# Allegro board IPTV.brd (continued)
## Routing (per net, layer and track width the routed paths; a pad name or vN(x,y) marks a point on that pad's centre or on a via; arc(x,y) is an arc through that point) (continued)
VCC_3.3V: length 38.9
  TOP w0.203: C333.1 129.39,49.72 129.39,49.31 128.08,48.01 U18.49 ; 119.8,50.1 120.24,50.1 120.44,49.9 U18.68 ; U18.20 121.24,40.89 v1(121.1,40.75) 120.84,41.01 U18.19 ; 117.32,46.52 118.72,46.52 119.01,46.81 U18.6 ; U18.30 125.24,41.15 125.45,40.93 125.48,40.93 v1(125.53,40.88) 125.54,40.89 125.54,40.93 125.64,41.02 U18.31 ; v1(125.67,50.63) 125.63,50.58 125.58,50.58 125.24,50.24 U18.56
  TOP w0.406: v1(131.36,36.99) C211.1 v1(130.28,35.85) ; v1(116.56,50.08) C245.1 116.59,50.86 C330.1 118.7,50.86 119.46,50.1 119.8,50.1 ; C333.1 v1(130.2,49.85) 131.11,49.85 C364.1 ; 117.32,46.52 C342.1 116.03,47.2 v1(116.03,47.21) ; R344.1 v1(116.69,47.15) ; C339.2 135.36,56.68 ; R320.1 v1(134.47,47.79) ; v1(115.8,52.08) R29.2 ; R338.2 v1(133.68,51.98) ; v1(117.35,50.18) R335.1 ; R321.1 v1(130.79,37.63) ; C371.2 v1(132.18,36.99)
  BOTTOM w0.406: v1(121.1,40.75) 121.04,40.7 121.01,40.7 120.73,40.42 C362.1 ; R321.1 v1(130.79,37.63) ; v1(119.79,39.66) 119.84,39.71 C362.1 ; C246.1 125.43,51.05 125.67,50.81 v1(125.67,50.63) ; C369.1 v1(134.47,47.79) ; C244.1 C362.1 ; C368.1 111.23,40.68 ; C218.1 133.68,51.98 v1(133.68,51.98) ; v1(125.53,40.88) 125.73,40.88 C370.1 C316.1 ; R335.1 v1(117.35,50.18)
  vias: v1(111.4,39.66) v1(111.4,38.9) v1(111.4,38.14) v1(111.4,37.38) v1(134.6,57.31) v1(134.6,56.55)
VCC_SCI\G: length 14.7
  TOP w0.406: U12.4 v1(25.46,43.62)
  BOTTOM w0.406: R8.1 18.71,37.57 Q9.3 v1(21.31,37.5) ; v1(22.99,36.07) R148.2 ; C146.1 v1(21.97,43.05) ; v1(22.99,38.61) R149.2 ; R152.2 v1(23.6,55.12) ; v1(22.99,33.66) R147.2 ; v1(22.73,52.7) R151.2 ; v1(22.73,51.05) R150.2 ; R290.2 v1(21.84,43.69) ; C148.1 v1(23.75,43.05)
VDD1_2_RF_LDO: length 32.9
  TOP w0.406: R353.1 135.23,48.93 C248.1 v1(135.36,49.99) 135.36,51.03 R346.1 ; v1(133.58,40.8) FB3.1 FB2.1
  BOTTOM w0.508: v1(128.75,40.55) 129.01,40.8 v1(133.58,40.8) 134.85,40.8 135.36,41.31 v1(135.36,49.99) ; v1(128.75,40.55) R326.1 ; v1(128.75,40.55) 128.75,38.53 128.11,37.88 123.93,37.88 123.42,38.39 R333.2
VDD25OUT: length 36.7
  TOP w0.254: U1.12 v1(95.47,75.16) ; U1.1 v1(93.02,80.66) ; U1.24 v1(101.31,75.09) ; U1.33 v1(101.63,79.16)
  TOP w0.508: L48.1 v1(103.48,68.77) L50.2 ; v1(95.47,75.16) 96.32,76.01 100.4,76.01 v1(101.31,75.09)
  BOTTOM w0.406: v1(93.02,80.66) 93.26,80.43 C419.1 ; C421.1 101.68,79.21 v1(101.63,79.16)
  BOTTOM w0.508: v1(93.02,80.66) 93.02,75.33 93.21,75.14 C420.1 95.45,75.14 v1(95.47,75.16) ; v1(101.63,79.16) 101.63,78.45 100.85,77.67 C415.1 100.83,77.38 C412.2 100.83,75.58 v1(101.31,75.09) 104.12,72.29 104.12,69.4 v1(103.48,68.77)
VDD_AUDIO: length 12.4
  TOP w0.254: U22.9 66.29,104.97 65.56,105.7 C75.1 R247.2 v1(65.76,106.84)
  BOTTOM w0.381: R174.2 61.68,104.71 C203.1 65.38,107.23 v1(65.76,106.84)
VDDPLL: length 3.6
  TOP w0.203: C340.1 129.31,45.88 129.18,45.75 v1(128.75,45.75) 128.61,45.61 U18.43
  BOTTOM w0.406: R326.2 128.73,44.61 128.73,45.72 v1(128.75,45.75)
2G_0_SW_OUT: length 7.8
  TOP w0.254: R336.1 131.34,30.39 U21.5 C377.1 137.79,29.25 C324.2
2G_1_SW_OUT: length 8.5
  TOP w0.254: C372.2 120.12,22.49 C375.1 121.28,22.52 121.28,29.15 U19.5 121.26,29.71 R345.1
43227_VDDIN_RFL: length 8.9
  TOP w0.152: C336.1 134.77,48.37 133.3,48.37 R320.2 132.69,47.76 129.6,47.76 128.24,46.41 U18.45
/WDG_RSTN\G: length 27.2
  TOP w0.127: 84.35,26.92 84.35,27.97 IC13.D6
  TOP w0.152: R356.1 77.7,8.67 78.46,9.44 78.46,16.17 80.87,18.58 83.92,18.58 84.56,19.21 84.56,25.44 84.35,25.65 84.35,26.92
AFE_INPUT_VDD1P2: length 4.1
  TOP w0.203: U18.42 129.26,45.21 v1(129.31,45.25)
  BOTTOM w0.152: C326.1 129.39,46.42 R352.2 129.39,45.33 v1(129.31,45.25)
AUDIO_L\G: length 8.4
  TOP w0.254: XS9.B2 71.26,111.2 70.87,110.81 C392.2 70.84,110.12 R257.1
AUDIO_OUTL\G: length 43.5
  TOP w0.254: IC13.AV7 83.03,55.69 83.03,77.51 70.64,89.9 70.64,90.61 R175.1 70.64,91.32 70.64,92.54 70.9,92.81 C268.1
AUDIO_OUTR\G: length 43.5
  TOP w0.254: IC13.AV8 82.52,55.74 82.52,77.3 70.13,89.69 70.13,90.64 R362.1 70.13,91.3 70.13,92.57 69.89,92.81 C393.2
AUDIO_R\G: length 8.4
  TOP w0.254: R361.2 69.7,110.12 C394.2 69.67,110.81 69.28,111.2 XS9.C2
AVS_VREF_IO\G: length 4.2
  TOP w0.508: C90.1 R15.1 49.89,89.57 49.44,89.13 C87.2
BOOT_SEL0\G: length 10.8
  TOP w0.127: 89.13,42.33 88.95,42.33 88.75,42.12 87.25,42.12 87.01,42.36 85.96,42.36 IC13.AB4
  TOP w0.152: R39.1 93.41,42.33 93.09,42.65 R58.2 90.72,42.9 90.42,42.61 R40.1 89.13,42.33
BOOT_SEL1\G: length 9.6
  TOP w0.127: 89.28,41.41 88.76,41.41 88.62,41.56 85.96,41.56 IC13.AA4
  TOP w0.152: 89.28,41.41 90.19,41.41 R57.2 90.42,40.9 90.65,40.67 92.13,40.67 v1(92.3,40.84)
  BOTTOM w0.152: R83.1 R155.1 92.28,40.82 v1(92.3,40.84)
BSC_M0_SCL\G: length 79.3
  TOP w0.152: R140.1 v1(46.48,115.95) 47,116.47 XP1.15 ; v1(46.84,111.69) 46.84,111.52 47.19,111.16 48.13,111.16 48.31,110.98 48.31,110.65 48.16,110.5 47.83,110.5 47.68,110.35 47.68,110.02 47.85,109.84 48.18,109.84 48.44,109.59 48.44,109.16 65.71,91.88 65.71,88.54 74.16,80.1 74.16,56.5 73.55,55.9 IC13.AV19
  BOTTOM w0.152: v1(46.48,115.95) D10.2 47.03,114.62 47.03,111.89 v1(46.84,111.69) U14.3
BSC_M0_SDA\G: length 80.5
  TOP w0.152: v1(47.53,111.69) 47.53,111.8 47.75,112.03 48.67,112.03 48.95,111.75 48.95,110.07 66.65,92.37 66.65,88.92 75.11,80.46 75.11,56.86 73.96,55.7 73.96,55.17 IC13.AU19 ; R141.1 v1(47.88,115.95) 47.5,116.33 XP1.16
  BOTTOM w0.152: U14.4 v1(47.53,111.69) 47.33,111.89 47.33,114.62 D11.2 v1(47.88,115.95)
CLK_50M_PHY0\G: length 2.3
  TOP w0.152: IC8.9 20.42,84.55 19.88,85.09 R240.2
CORE0_RX: length 33.3
  TOP w0.152: v1(115.89,33.92) 115.89,42.8 117.06,43.97 119.1,43.97 119.13,44.01 U18.13 ; U21.6 C361.2 v1(130.81,32.45)
  BOTTOM w0.152: v1(115.89,33.92) 115.89,32.78 117.9,30.77 128.75,30.77 130.43,32.45 v1(130.81,32.45)
CORE0_TX: length 33.3
  TOP w0.152: v1(131.11,28.33) C366.2 U21.4 ; v1(116.4,31.25) 116.4,42.67 117.33,43.61 U18.14
  BOTTOM w0.152: v1(131.11,28.33) 124.71,28.33 124.21,28.84 118.81,28.84 v1(116.4,31.25)
CORE1_RX: length 18.1
  TOP w0.152: U18.16 118.59,42.81 118.53,42.86 117.89,42.86 117.54,42.51 117.54,30.43 118.75,29.22 C337.2 119.28,29.17 U19.4
CORE1_TX: length 23.2
  TOP w0.152: v1(116.91,33.92) 116.91,42.42 117.69,43.21 U18.15 ; v1(123.17,31.38) C344.2 123.11,29.17 U19.6
  BOTTOM w0.152: v1(123.17,31.38) 118.05,31.38 116.91,32.52 v1(116.91,33.92)
CVBS\G: length 47.6
  TOP w0.152: IC13.AV13 78.36,55.57 78.36,56.17 78.21,56.32 v1(78.21,77) ; v1(92.65,87.62) C341.1 92.65,91.56 R95.1 R92.1 92.59,94.8 IC9.3
  BOTTOM w0.152: v1(92.65,87.62) 88.82,87.62 v1(78.21,77)
CVBS_OUT\G: length 10.6
  TOP w0.381: D16.3 90.95,104.67 R163.2 90.97,106.41 C36.2 90.86,110.81 XS9.A2
DDRA_ADDR0: length 31.6
  TOP w0.102: U9.N3 38.78,45 38.61,45.17 38.61,47.9 38.74,48.03 38.74,48.72
  TOP w0.152: R205.1 v1(51.03,50.55) ; v1(43.9,51.48) 43.9,50.11 43.65,49.86 38.9,49.86 38.74,49.69 38.74,48.72
  BOTTOM w0.152: v1(51.03,50.55) 51.03,51.04 50.86,51.21 50.43,51.21 50.28,51.35 50.28,52.31 50.13,52.46 49.83,52.46 49.68,52.31 49.68,51.59 49.52,51.43 49.22,51.43 49.07,51.59 49.07,52.31 48.91,52.46 48.61,52.46 48.46,52.31 48.46,51.6 48.29,51.43 48,51.43 47.85,51.59 47.85,52.29 47.67,52.46 42.92,52.46 42.72,52.27 42.72,51.94 42.37,51.58 42.37,51.38 42.6,51.15 42.81,51.15 43.51,51.85 43.74,51.85 43.9,51.69 v1(43.9,51.48)
DDRA_ADDR0_R: length 3.8
  TOP w0.127: 57.02,49.95 58.34,49.95 IC13.AL38
  TOP w0.152: R205.2 55.16,50.55 55.76,49.95 57.02,49.95
DDRA_ADDR1: length 32.1
  TOP w0.152: v2(35.72,46.2) 36.12,45.8 U9.P7 ; R217.1 50.36,43.12 48.43,45.05 47.33,45.05 46.91,44.63 46.91,43.66 46.52,43.27 46.14,43.27 45.82,43.59 45.82,45.82 43.47,48.17 v2(41.07,48.17)
  BOTTOM w0.152: v2(41.07,48.17) 39.78,49.47 39.78,52.68 39.33,53.13 36.99,53.13 36.58,52.71 36.58,46.8 35.98,46.2 v2(35.72,46.2)
DDRA_ADDR1_R: length 8
  TOP w0.127: IC13.AB36 59.54,43.18 58.19,43.18 57.75,43.61 57.56,43.61
  TOP w0.152: 57.56,43.61 56.76,43.61 56.26,43.12 R217.2
DDRA_ADDR2: length 30.8
  TOP w0.102: 39.14,48.72 39.14,47.86 38.94,47.66 38.94,46.18 U9.P3
  TOP w0.152: R206.1 50.27,51.12 49.86,51.52 49.86,52.61 49.54,52.93 48.76,52.93 48.44,52.62 48.44,50.29 48.26,50.11 48.01,50.11 47.83,50.29 47.83,52.61 47.51,52.93 46.7,52.93 46.41,52.64 46.41,50.3 46.23,50.13 45.98,50.13 45.8,50.3 45.8,52.61 45.48,52.93 44.74,52.93 44.38,52.57 44.38,49.77 44.06,49.45 39.36,49.45 39.14,49.24 39.14,48.72
DDRA_ADDR2_R: length 7.1
  TOP w0.127: 57.56,50.36 58.76,50.36 IC13.AL37
  TOP w0.152: R206.2 55.7,51.12 56.46,50.36 57.56,50.36
DDRA_ADDR3: length 31.4
  TOP w0.127: v1(42.11,45.05) 41.77,45.4 40.51,45.4 U9.N2
  TOP w0.152: v1(53.19,43.69) R216.1
  BOTTOM w0.152: v1(42.11,45.05) 42.11,45.66 42.3,45.84 42.54,45.84 42.55,45.83 42.72,45.66 42.72,45.18 42.9,45 43.15,45 43.33,45.18 43.33,45.66 43.5,45.83 43.77,45.83 43.94,45.66 43.94,45.18 44.12,45 44.37,45 44.55,45.18 44.55,45.66 44.72,45.83 44.99,45.83 45.16,45.66 45.16,45.18 45.34,45 45.59,45 45.77,45.18 45.77,45.66 45.94,45.83 46.21,45.83 46.38,45.66 46.38,45.18 46.56,45 46.81,45 46.99,45.18 46.99,45.66 47.16,45.83 47.43,45.83 47.6,45.66 47.6,45.18 47.78,45 48.03,45 48.21,45.18 48.21,45.66 48.38,45.83 48.65,45.83 48.82,45.66 48.82,45.18 49,45 52.37,45 53,44.37 53.84,44.37 54.21,44.75 54.21,47.29 54.38,47.46 54.64,47.46 54.82,47.27 54.82,44.03 54.48,43.69 v1(53.19,43.69)
DDRA_ADDR3_R: length 5.7
  TOP w0.152: IC13.AE36 58.8,44.02 56.31,44.02 55.98,43.69 R216.2
DDRA_ADDR4: length 30.9
  TOP w0.127: U9.P8 34.92,46.2 v2(34.12,46.2)
  TOP w0.152: v1(50.78,48.15) 51.28,48.15 51.59,47.84 R210.1
  BOTTOM w0.102: 36.17,47.33 36.17,46.91 35.86,46.61 34.53,46.61 v2(34.12,46.2)
  BOTTOM w0.152: v1(50.78,48.15) 50.66,48.15 49.99,47.47 48.87,47.47 48.39,47.95 48.39,48.43 47.82,48.99 40.82,48.99 40.18,49.63 40.18,53.17 39.83,53.53 36.58,53.53 36.17,53.12 36.17,47.33
DDRA_ADDR4_R: length 6.1
  TOP w0.127: 57.02,47.69 57.51,47.69 58.19,48.37 IC13.AJ38
  TOP w0.152: R210.2 57.02,47.69
DDRA_ADDR5: length 32.2
  TOP w0.127: U9.P2 40.12,46.07 40.25,46.21 41.91,46.21
  TOP w0.152: 41.91,46.21 42.37,46.21 42.57,46.01 42.57,45.18 42.75,45 43.03,45 43.18,45.15 43.18,46.65 v1(43.13,46.7) ; v1(50.44,46.7) 50.44,44.18 50.6,44.03 50.9,44.03 51.05,44.18 51.05,45.27 51.18,45.4 R215.1
  BOTTOM w0.152: v1(50.44,46.7) 50.44,46.58 50.6,46.42 51.16,46.42 51.31,46.58 51.31,47.76 51.51,47.97 51.7,47.97 51.92,47.75 51.92,46.65 52.14,46.42 52.57,46.42 52.73,46.27 52.73,45.99 52.56,45.81 49.81,45.81 49.63,45.99 49.63,46.47 49.45,46.65 46.36,46.65 46.18,46.83 46.18,47.6 46,47.77 45.75,47.77 45.57,47.6 45.57,46.83 45.39,46.65 45.14,46.65 44.96,46.83 44.96,47.6 44.78,47.77 44.53,47.77 44.35,47.6 44.35,46.83 44.17,46.65 43.92,46.65 43.74,46.83 43.74,47.64 43.6,47.77 43.28,47.77 43.13,47.62 v1(43.13,46.7)
DDRA_ADDR5_R: length 7.6
  TOP w0.127: IC13.AF36 59.55,45.57 58.03,45.57 57.86,45.4 57.63,45.4
  TOP w0.152: R215.2 57.63,45.4
DDRA_ADDR6: length 32.4
  TOP w0.127: v2(34.92,47) U9.R8
  TOP w0.152: v1(53.19,47.12) R211.1
  BOTTOM w0.152: v1(53.19,47.12) 52.73,47.57 52.73,48.14 51.19,49.68 49.69,49.68 49.15,50.21 41.63,50.21 41.4,50.44 41.4,53.97 40.62,54.75 35.68,54.75 34.9,53.97 34.9,47.02 v2(34.92,47)
DDRA_ADDR6_R: length 4.8
  TOP w0.127: IC13.AJ37 58.75,47.96 58.19,47.96 57.96,47.73 57.96,47.73 57.35,47.12 57.02,47.12
  TOP w0.152: R211.2 57.02,47.12
DDRA_ADDR7: length 32.3
  TOP w0.127: v1(42.58,47.02) 42.57,47.01 40.53,47.01 U9.R2
  TOP w0.152: v1(47.52,47.15) 47.52,46.7 47.34,46.52 46.94,46.52 46.74,46.32 46.74,45.66 46.94,45.45 47.9,45.45 48.13,45.68 48.13,48.62 48.31,48.8 48.57,48.8 48.74,48.63 48.74,45.31 48.91,45.14 49.2,45.14 49.35,45.29 49.35,48.88 49.53,49.06 49.78,49.06 49.96,48.88 49.96,44.09 50.43,43.62 51.36,43.62 51.59,43.85 R214.1
  BOTTOM w0.152: v1(47.52,47.15) 46.76,47.15 46.58,47.33 46.58,48 46.41,48.18 42.77,48.18 42.58,47.98 v1(42.58,47.02)
DDRA_ADDR7_R: length 7
  TOP w0.152: R214.2 55.69,44.26 55.86,44.42 58.41,44.42 IC13.AE37
DDRA_ADDR8: length 31.4
  TOP w0.152: v2(34.49,48.33) 34.49,48.23 U9.T8 ; R209.1 v1(53.19,48.26)
  BOTTOM w0.152: v2(34.49,48.33) 34.49,54.14 35.51,55.16 40.79,55.16 41.81,54.14 41.81,51.37 42.55,50.62 49.32,50.62 49.85,50.09 51.36,50.09 v1(53.19,48.26)
DDRA_ADDR8_R: length 6.3
  TOP w0.127: 57.02,48.26 57.63,48.26 58.15,48.78 60.36,48.78 IC13.AK35
  TOP w0.152: R209.2 57.02,48.26
DDRA_ADDR9: length 31.6
  TOP w0.102: v2(40.03,48.14) 40.03,47.85 39.71,47.53 39.71,46.99 U9.R3
  TOP w0.152: R212.1 51.03,46.55 50.9,46.67 50.9,47.38 v1(50.83,47.46)
  BOTTOM w0.152: v1(50.83,47.46) 50.55,47.46 50.15,47.06 48.7,47.06 47.18,48.59 42.05,48.59 41.76,48.3 41.76,47.81 41.48,47.54 38.2,47.54 38,47.74 38,47.97 38.18,48.14 38.51,48.14 38.68,48.32 38.68,48.58 38.51,48.75 38.18,48.75 38,48.93 38,49.19 38.18,49.36 38.51,49.36 38.68,49.54 38.68,49.79 38.51,49.97 38.18,49.97 38,50.15 38,50.4 38.18,50.58 38.51,50.58 38.68,50.76 38.68,51.01 38.51,51.19 38.18,51.19 38,51.37 38,52.51 38.2,52.72 39.17,52.72 39.37,52.51 39.37,48.81 v2(40.03,48.14)
DDRA_ADDR9_R: length 6.8
  TOP w0.152: R212.2 55.37,46.55 55.46,46.46 58.66,46.46 IC13.AF37
DDRA_ADDR10: length 35.4
  TOP w0.152: R218.1 v1(50.45,42.55) ; v2(35.72,43.8) 36.12,43.4 U9.L7
  BOTTOM w0.152: v2(35.72,43.8) 35.74,43.78 41.94,43.78 42.35,44.19 46.58,44.19 46.79,43.98 46.79,42.25 46.97,42.07 47.22,42.07 47.4,42.25 47.4,44.01 47.58,44.19 47.83,44.19 48.01,44.01 48.01,42.17 48.19,41.99 48.45,41.99 48.62,42.16 48.62,44.01 48.8,44.19 49.05,44.19 49.23,44.01 49.23,42.17 49.41,41.99 49.66,41.99 49.84,42.16 49.84,44.01 50.02,44.19 51.97,44.19 52.15,44.01 52.15,43.76 51.97,43.58 50.63,43.58 50.45,43.4 v1(50.45,42.55)
DDRA_ADDR10_R: length 6.3
  TOP w0.127: 57.4,42.55 57.62,42.55 57.81,42.36 60.52,42.36 60.75,42.59 IC13.AB35
  TOP w0.152: R218.2 57.4,42.55
DDRA_ADDR11: length 29.2
  TOP w0.152: R208.1 50.79,48.83 v1(50.78,48.82) ; v2(35.72,47) U9.R7
  BOTTOM w0.152: v2(35.72,47) 35.76,47.05 35.76,53.68 36.02,53.94 40.28,53.94 40.59,53.63 40.59,49.8 40.99,49.4 48.54,49.4 48.79,49.15 48.79,48.12 49.04,47.87 49.82,47.87 50.21,48.27 50.21,48.68 50.35,48.82 v1(50.78,48.82)
DDRA_ADDR11_R: length 7.6
  TOP w0.127: IC13.AK36 59.82,49.03 57.79,49.03 57.49,48.73 57.02,48.73
  TOP w0.152: 57.02,48.73 55.25,48.73 55.16,48.83 R208.2
DDRA_ADDR12: length 34.5
  TOP w0.152: U9.N7 36.12,45 v2(35.72,45.4) ; R213.1 v1(53.19,44.83)
  BOTTOM w0.152: v1(53.19,44.83) 53.19,45.25 53.03,45.41 49.4,45.41 49.23,45.58 49.23,46.02 49,46.25 42.08,46.25 41.91,46.42 41.91,46.94 41.72,47.13 38.38,47.13 38.2,46.95 38.2,46.34 38.02,46.16 37.77,46.16 37.59,46.34 37.59,52.54 37.43,52.7 37.15,52.7 36.98,52.54 36.98,46.06 36.72,45.8 36.01,45.8 35.72,45.51 v2(35.72,45.4)
DDRA_ADDR12_R: length 3.7
  TOP w0.152: R213.2 58.02,44.83 IC13.AE38
DDRA_ADDR13: length 34
  TOP w0.102: 39.55,48.72 39.55,47.84 39.32,47.61 U9.T3
  TOP w0.152: 39.55,48.72 39.55,48.83 39.77,49.05 44.6,49.05 44.78,49.23 44.78,52.35 44.96,52.53 45.21,52.53 45.39,52.35 45.39,49.56 45.64,49.31 46.58,49.31 46.81,49.54 46.81,52.35 46.99,52.53 47.25,52.53 47.42,52.35 47.42,49.44 47.65,49.21 48.61,49.21 48.85,49.44 48.85,52.35 49.02,52.53 49.28,52.53 49.46,52.35 49.46,49.97 50.02,49.4 R207.1
DDRA_ADDR13_R: length 6.4
  TOP w0.127: IC13.AL35 60.34,49.56 59.79,49.56 59.52,49.28 57.61,49.28 57.47,49.14 57.02,49.14
  TOP w0.152: R207.2 55.16,49.4 55.42,49.14 57.02,49.14
DDRA_ADDR14: length 34.1
  TOP w0.152: U9.T7 36.1,47.4 v2(35.33,48.17) ; R200.1 v1(53.19,45.97)
  BOTTOM w0.152: v2(35.33,48.17) 35.33,53.82 35.85,54.34 40.45,54.34 41,53.8 41,50.06 41.25,49.81 48.99,49.81 49.2,49.59 49.2,48.45 49.37,48.28 49.61,48.28 49.81,48.47 49.81,49.08 50,49.28 51.02,49.28 51.31,48.99 51.31,48.6 51.54,48.37 51.93,48.37 52.32,47.97 52.32,47 52.5,46.83 52.83,46.83 53.19,46.47 v1(53.19,45.97)
DDRA_ADDR14_R: length 3.5
  TOP w0.152: R200.2 58.34,45.97 IC13.AF38
DDRA_BA0: length 35.7
  TOP w0.127: 42.1,44.6 40.51,44.6 U9.M2
  TOP w0.152: 42.1,44.6 43.41,44.6 43.59,44.77 43.59,46.86 43.76,47.04 44.03,47.04 44.2,46.87 44.2,44.77 44.37,44.6 44.63,44.6 44.81,44.77 44.81,45.64 44.98,45.82 45.24,45.82 45.42,45.64 45.42,42.11 45.59,41.94 45.92,41.94 46.1,42.11 46.1,42.68 46.28,42.86 46.53,42.86 46.71,42.68 46.71,42.16 46.89,41.99 47.13,41.99 47.32,42.17 47.32,44.46 47.5,44.64 47.75,44.64 47.93,44.46 47.93,41.16 48.1,40.99 48.37,40.99 48.54,41.16 48.54,43.75 48.72,43.93 48.97,43.93 49.15,43.75 49.15,41.06 49.31,40.89 49.58,40.89 49.76,41.07 49.76,41.95 49.94,42.12 50.19,42.12 50.37,41.95 50.37,41.07 50.54,40.89 R221.1
DDRA_BA0_R: length 7
  TOP w0.127: IC13.Y37 58.75,40.76 58.06,40.76 57.85,40.55 57.63,40.55
  TOP w0.152: 57.63,40.55 57,40.55 56.65,40.89 R221.2
DDRA_BA1: length 32.7
  TOP w0.152: v2(34.92,45.4) 34.92,45.4 U9.N8 ; v1(50.92,42.09) 51.04,41.97 R219.1
  BOTTOM w0.152: v2(34.92,45.4) 34.92,44.6 35.13,44.39 35.94,44.39 36.11,44.55 36.11,45.21 36.29,45.39 36.54,45.39 36.72,45.21 36.72,44.37 36.9,44.19 37.15,44.19 37.33,44.37 37.33,45.58 37.51,45.76 37.76,45.76 37.94,45.58 37.94,44.37 38.12,44.19 38.37,44.19 38.55,44.37 38.55,45.62 38.72,45.8 38.98,45.8 39.16,45.62 39.16,44.36 39.32,44.2 40.88,44.2 41.28,44.6 52.2,44.6 52.56,44.24 52.56,43.59 52.38,43.41 52.38,43.41 52.15,43.18 52.15,42.31 51.98,42.14 51.72,42.14 51.54,42.33 51.54,43.01 51.38,43.17 51.09,43.17 50.92,43.01 v1(50.92,42.09)
DDRA_BA1_R: length 7.4
  TOP w0.127: IC13.AA36 59.94,41.98 57.56,41.98
  TOP w0.152: R219.2 52.56,41.98 57.56,41.98
DDRA_BA2: length 35.7
  TOP w0.127: U9.M3 39.73,43.8 41.08,43.8 41.66,43.8 42.05,44.19 42.5,44.19
  TOP w0.152: 42.5,44.19 44.72,44.19 45.01,43.9 45.01,41.83 45.36,41.48 v1(46.79,41.48) ; R220.1 v1(53.19,41.4)
  BOTTOM w0.152: v1(46.79,41.48) 47.09,41.17 52.16,41.17 53.12,42.14 55.33,42.14 55.64,42.46 55.64,45.38 55.82,45.56 57.45,45.56 57.63,45.38 57.63,45.13 57.45,44.95 56.43,44.95 56.25,44.77 56.25,44.52 56.43,44.34 57.45,44.34 57.63,44.16 57.63,43.91 57.45,43.73 56.49,43.73 56.25,43.49 56.25,41.71 55.95,41.4 v1(53.19,41.4)
DDRA_BA2_R: length 6.1
  TOP w0.127: IC13.AA35 60.36,41.57 57.56,41.57
  TOP w0.152: R220.2 55.01,41.57 57.56,41.57
DDRA_CASN: length 27.8
  TOP w0.102: 38.33,48.72 38.33,43.05 38.78,42.6 U9.K3
  TOP w0.152: R204.1 50.67,49.97 50.39,50.25 v1(50.39,50.58) ; 38.33,48.72 38.33,49.96 38.63,50.27 43.26,50.27 43.4,50.41 v1(43.4,51.09)
  BOTTOM w0.152: v1(43.4,51.09) 43.45,51.04 43.46,51.04 43.47,51.03 44.19,51.03 44.39,51.23 44.39,51.9 44.55,52.06 44.85,52.06 45,51.9 45,51.21 45.18,51.03 45.43,51.03 45.61,51.21 45.61,51.9 45.76,52.06 46.07,52.06 46.22,51.9 46.22,51.21 46.4,51.03 46.65,51.03 46.83,51.21 46.83,51.9 46.98,52.06 47.29,52.06 47.44,51.9 47.44,51.23 47.65,51.03 49.95,51.03 v1(50.39,50.58)
DDRA_CASN_R: length 7.8
  TOP w0.127: IC13.AL36 59.7,49.97 59.31,49.58 57.56,49.58 57.53,49.54 57.19,49.54
  TOP w0.152: R204.2 55.16,49.97 55.59,49.54 57.19,49.54
DDRA_CKE0: length 39.8
  TOP w0.152: IC13.Y38 57.56,41.17 v1(57.53,41.14) ; U9.K9 v2(34.12,42.2)
  BOTTOM w0.152: R188.2 57.98,41.59 v1(57.53,41.14) 57.32,40.93 57.32,39.53 57.15,39.37 56.89,39.37 56.71,39.55 56.71,40.46 56.52,40.65 56.26,40.65 56.1,40.49 56.1,39.55 55.92,39.37 51.02,39.37 50.84,39.19 50.84,37.99 50.66,37.81 50.41,37.81 50.23,37.99 50.23,39.04 50.05,39.22 49.8,39.22 49.62,39.04 49.62,37.99 49.44,37.81 49.19,37.81 49.01,37.99 49.01,39.04 48.84,39.22 48.58,39.22 48.4,39.04 48.4,37.99 48.23,37.81 47.97,37.81 47.79,37.99 47.79,39.19 47.62,39.37 43.33,39.37 43.08,39.62 43.08,41.57 42.84,41.81 38.47,41.81 37.47,42.81 34.73,42.81 v2(34.12,42.2)
DDRA_CKN0: length 35.2
  TOP w0.152: v1(42.44,53.61) 42.21,53.38 41.44,53.38 R629.1 40.59,53.37 40.31,53.37 R628.2 39.45,53.37 39.09,53.37 R631.1 37.87,53.37 37.59,53.37 36.58,52.35 36.58,42.47 36.46,42.35 36.37,42.35 U9.K7
  BOTTOM w0.152: v1(42.44,53.61) 42.67,53.38 50.59,53.38 56.21,47.75 56.52,47.75 R259.1
DDRA_CKN0_R: length 3.3
  TOP w0.127: IC13.AH35 v2(60.35,47.97)
  BOTTOM w0.152: R259.2 58.33,47.72 60.1,47.72 v2(60.35,47.97)
DDRA_CKP0: length 35.1
  TOP w0.152: v1(42.44,52.84) 42.21,53.07 41.44,53.07 R626.1 40.61,53.06 40.28,53.06 R627.2 39.47,53.06 39.09,53.06 R631.2 37.87,53.06 37.72,53.06 36.88,52.22 36.88,42.34 36.59,42.05 36.37,42.05 U9.J7
  BOTTOM w0.152: v1(42.44,52.84) 42.67,53.07 50.46,53.07 56.08,47.45 56.49,47.45 R260.1
DDRA_CKP0_R: length 3.3
  TOP w0.127: IC13.AH36 v2(60.35,47.17)
  BOTTOM w0.152: R260.2 58.29,47.41 60.1,47.41 v2(60.35,47.17)
DDRA_CSN0: length 31.4
  TOP w0.102: U9.L2 40.5,43.02 41.5,43.02 41.96,43.48
  TOP w0.152: 41.96,43.48 42.27,43.78 43.61,43.78 44.6,42.79 44.6,41.67 45.28,40.99 47.02,40.99 47.47,41.44 v1(47.47,41.63) ; R203.1 v1(50.9,51.69)
  BOTTOM w0.152: v1(47.47,41.63) 47.52,41.58 51.99,41.58 53.69,43.28 54.65,43.28 55.23,43.86 55.23,47.44 50.98,51.69 v1(50.9,51.69)
DDRA_CSN0_R: length 3.9
  TOP w0.127: IC13.AM38 58.35,50.76 57.56,50.76
  TOP w0.152: R203.2 55.77,51.69 56.69,50.76 57.56,50.76
DDRA_DM0: length 35.3
  TOP w0.152: v2(59.55,37.56) 59.15,37.96 IC13.T37 ; U9.E7 36.12,38.6 v2(35.72,38.2)
  BOTTOM w0.152: v2(59.55,37.56) 59.03,37.04 59.03,35.11 54.48,30.56 39.44,30.56 39.43,30.55 37.98,30.55 36.2,32.33 36.2,37.72 v2(35.72,38.2)
DDRA_DM1: length 36.6
  TOP w0.127: U9.D3 39.32,37.8 v2(39.72,37.4)
  TOP w0.152: v1(56.94,36.5) 57.16,36.5 58.1,35.57 IC13.N38
  BOTTOM w0.152: v1(56.94,36.5) 56.94,34.92 56.76,34.74 56.51,34.74 56.33,34.92 56.33,36.41 56.15,36.59 55.9,36.59 55.72,36.41 55.72,34.58 55.5,34.36 53.66,34.36 53.48,34.54 53.48,36.41 53.31,36.59 53.05,36.59 52.87,36.41 52.87,34.54 52.7,34.36 52.44,34.36 52.27,34.54 52.27,36.41 52.09,36.59 51.83,36.59 51.66,36.41 51.66,34.54 51.48,34.36 51.22,34.36 51.05,34.54 51.05,36.41 50.87,36.59 45.5,36.59 45.34,36.74 45.34,37.76 45.15,37.95 39.85,37.95 39.72,37.81 v2(39.72,37.4)
DDRA_DQ0: length 39.2
  TOP w0.102: U9.F8 34.94,39.78 33.41,39.78 33.4,39.78
  TOP w0.127: IC13.H37 58.76,31.17 58.53,31.17 58.52,31.16 57.05,31.16
  TOP w0.152: 57.05,31.16 54.26,31.16 53.95,31.47 53.95,32.87 53.76,33.06 53.52,33.06 53.34,32.88 53.34,32.49 53.16,32.31 52.91,32.31 52.73,32.49 52.73,32.88 52.55,33.06 52.3,33.06 52.12,32.88 52.12,31.39 51.89,31.16 36.87,31.16 33.02,35.01 33.02,39.4 33.4,39.78
DDRA_DQ1: length 38.5
  TOP w0.102: U9.F7 35.74,39.02 34.07,39.02 34.06,39.02 33.68,39.02 33.43,38.76 33.43,38.35
  TOP w0.152: IC13.H38 54.64,31.57 54.36,31.85 54.36,33.2 54.09,33.46 51.98,33.46 51.71,33.2 51.71,31.88 51.4,31.57 37.04,31.57 35.86,32.74 35.86,34.52 35.69,34.7 35.42,34.7 35.26,34.53 35.26,34.01 35.05,33.81 34.83,33.81 34.65,33.99 34.65,34.55 34.45,34.75 33.86,34.75 33.43,35.18 33.43,38.35
DDRA_DQ2: length 37.8
  TOP w0.102: 33.4,40.35 33.66,40.61 35.72,40.61 U9.H7
  TOP w0.152: 33.4,40.35 32.61,39.56 32.61,34.84 36.7,30.75 52.5,30.75 52.68,30.93 52.68,31.56 52.86,31.73 53.11,31.73 53.29,31.56 53.29,30.93 53.47,30.75 58.34,30.75 IC13.G38
DDRA_DQ3: length 38
  TOP w0.102: 33.4,41.05 33.77,41.42 34.9,41.42 U9.H8
  TOP w0.152: IC13.G37 58.73,30.35 36.53,30.35 32.21,34.67 32.21,35.01 32.21,39.86 33.4,41.05
DDRA_DQ4: length 34.8
  TOP w0.127: v1(42.19,38.51) 41.83,38.14 41.37,38.14 41.31,38.2 39.73,38.2 U9.E3
  TOP w0.152: IC13.T38 58.35,37.97 58.66,38.28 58.66,38.28 v2(58.75,38.36)
  BOTTOM w0.152: v1(42.19,38.51) 45.52,38.51 45.76,38.26 45.76,37.17 45.94,36.99 46.19,36.99 46.37,37.17 46.37,38.38 46.55,38.56 46.8,38.56 46.98,38.38 46.98,37.19 47.17,36.99 53.7,36.99 53.89,36.8 53.89,34.96 54.08,34.77 55.12,34.77 55.31,34.96 55.31,38.4 55.47,38.56 55.74,38.56 55.92,38.38 55.92,37.22 56.1,37.05 56.35,37.05 56.53,37.22 56.53,38.38 56.71,38.56 56.96,38.56 57.14,38.38 57.14,37.27 57.32,37.1 57.57,37.1 57.75,37.27 57.75,38.19 57.93,38.36 v2(58.75,38.36)
DDRA_DQ5: length 37.6
  TOP w0.127: 41.91,39.8 40.53,39.8 U9.G2
  TOP w0.152: IC13.U38 55.6,38.77 55.42,38.59 55.42,37.83 55.27,37.68 54.99,37.68 54.81,37.86 54.81,38.61 54.66,38.77 54.36,38.77 54.2,38.61 54.2,36.79 54.03,36.61 53.77,36.61 53.59,36.79 53.59,38.61 53.44,38.77 53.14,38.77 52.98,38.61 52.98,36.79 52.81,36.61 52.55,36.61 52.37,36.79 52.37,38.59 52.2,38.77 50.32,38.77 50.14,38.59 50.14,36.79 49.96,36.61 49.71,36.61 49.53,36.79 49.53,38.72 49.35,38.89 47.47,38.89 47.29,38.72 47.29,36.75 47.16,36.61 46.84,36.61 46.69,36.76 46.69,39.97 46.47,40.18 42.58,40.18 42.2,39.8 41.91,39.8
DDRA_DQ6: length 39.2
  TOP w0.102: U9.H3 39.74,40.58 42.01,40.58
  TOP w0.152: 42.01,40.58 42.19,40.58 42.37,40.76 42.37,43.2 42.55,43.38 42.8,43.38 42.98,43.2 42.98,40.76 43.16,40.58 43.41,40.58 43.59,40.76 43.59,42.2 43.76,42.38 44.02,42.38 44.2,42.2 44.2,40.76 44.37,40.58 46.91,40.58 47.09,40.4 47.09,39.48 47.27,39.3 47.52,39.3 47.7,39.48 47.7,40.4 47.88,40.58 48.13,40.58 48.31,40.4 48.31,39.48 48.49,39.3 48.74,39.3 48.92,39.48 48.92,40.31 49.1,40.49 49.35,40.49 49.53,40.31 49.53,39.35 49.71,39.17 49.96,39.17 50.14,39.35 50.14,40.31 50.32,40.49 50.57,40.49 50.75,40.31 50.75,39.35 50.93,39.17 51.18,39.17 51.36,39.35 51.36,40.12 51.54,40.3 51.79,40.3 51.97,40.12 51.97,39.35 52.15,39.17 52.4,39.17 52.58,39.35 52.58,39.61 52.76,39.79 53.01,39.79 53.19,39.61 53.19,39.35 53.37,39.17 53.62,39.17 53.8,39.35 53.8,39.48 53.98,39.66 54.23,39.66 54.41,39.48 54.41,39.35 54.59,39.17 58.75,39.17 IC13.U37
DDRA_DQ7: length 40.5
  TOP w0.127: U9.F2 40.53,39 41.94,39 v1(42.16,39.22)
  TOP w0.152: v2(59.55,39.17) 59.95,38.77 IC13.U36
  BOTTOM w0.152: v2(59.55,39.17) 59.55,40.24 59.37,40.42 59.12,40.42 58.94,40.24 58.94,39.09 58.76,38.91 58.51,38.91 58.33,39.09 58.33,40.24 58.15,40.42 57.9,40.42 57.72,40.24 57.72,39.22 57.47,38.96 55.16,38.96 54.91,38.71 54.91,35.37 54.71,35.18 54.5,35.18 54.3,35.38 54.3,38.79 54.12,38.96 53.87,38.96 53.69,38.79 53.69,37.58 53.51,37.4 53.26,37.4 53.08,37.58 53.08,38.79 52.9,38.96 52.65,38.96 52.47,38.79 52.47,37.58 52.29,37.4 52.04,37.4 51.86,37.58 51.86,38.79 51.68,38.96 51.43,38.96 51.25,38.79 51.25,37.58 51.07,37.4 47.65,37.4 47.39,37.67 47.39,38.75 47.17,38.96 42.42,38.96 v1(42.16,39.22)
DDRA_DQ8: length 35.6
  TOP w0.127: v2(59.44,34.47) 59.54,34.36 59.55,34.36 59.95,33.97 IC13.L36
  TOP w0.152: U9.D7 36.12,37.8 v2(35.72,37.4)
  BOTTOM w0.152: v2(35.72,37.4) 35.79,37.33 35.79,32.17 37.81,30.15 39.6,30.15 39.61,30.15 55.36,30.15 55.54,30.33 55.54,31 55.71,31.18 55.97,31.18 56.14,31 56.14,30.33 56.32,30.15 56.58,30.15 56.75,30.33 56.75,32.26 58.97,34.47 v2(59.44,34.47)
DDRA_DQ9: length 39.2
  TOP w0.127: 36.59,35.81 35.71,35.81 U9.B8
  TOP w0.152: 36.59,35.81 37.65,35.81 37.9,35.56 37.9,32.6 38.12,32.38 44.63,32.38 44.81,32.56 44.81,34.1 44.98,34.27 45.24,34.27 45.42,34.1 45.42,32.56 45.59,32.38 45.85,32.38 46.02,32.56 46.02,34.1 46.2,34.27 46.46,34.27 46.63,34.1 46.63,32.56 46.81,32.38 47.07,32.38 47.24,32.55 47.24,34.1 47.42,34.27 47.68,34.27 47.85,34.1 47.85,32.56 48.03,32.38 48.28,32.38 48.46,32.56 48.46,34.1 48.64,34.27 58.09,34.27 58.18,34.37 58.75,34.37 IC13.L37
DDRA_DQ10: length 39.1
  TOP w0.152: U9.A7 36.27,35.25 36.27,33.36 36.43,33.2 36.73,33.2 36.88,33.35 36.88,35.22 37.06,35.4 37.32,35.4 37.49,35.23 37.49,32.23 37.75,31.97 48.45,31.97 48.87,32.39 48.87,33.69 49.05,33.87 49.3,33.87 49.48,33.69 49.48,32.15 49.66,31.97 49.91,31.97 50.09,32.15 50.09,33.69 50.27,33.87 50.52,33.87 50.7,33.69 50.7,32.15 50.88,31.97 51.13,31.97 51.31,32.15 51.31,33.64 51.54,33.87 55.67,33.87 55.85,33.69 55.85,33.5 56.02,33.32 56.28,33.32 56.46,33.5 56.46,33.69 56.63,33.87 56.89,33.87 57.06,33.69 57.06,33.5 57.24,33.32 57.5,33.32 57.67,33.5 57.67,33.69 57.85,33.87 58.25,33.87 IC13.L38
DDRA_DQ11: length 37.3
  TOP w0.152: v2(34.92,36.6) 35.32,37 U9.C8 ; v2(58.75,33.56) 58.35,33.17 IC13.K38
  BOTTOM w0.152: v2(58.75,33.56) 58.38,33.19 58.38,30.15 58.16,29.93 57.96,29.93 57.77,30.12 57.77,31.79 57.59,31.96 57.34,31.96 57.16,31.79 57.16,30.04 56.86,29.74 39.77,29.74 39.77,29.74 37.64,29.74 35.38,32 35.38,36.14 v2(34.92,36.6)
DDRA_DQ12: length 40.1
  TOP w0.127: 57.55,37.34 57.55,36.61 58.21,35.96 58.75,35.96 IC13.P37
  TOP w0.152: U9.A3 39.44,35.28 39.44,34.28 39.82,33.9 42.66,33.9 43.03,34.28 43.03,38.73 43.03,39.08 43.32,39.36 45.59,39.36 45.87,39.08 45.87,36.08 46.15,35.8 47.8,35.8 48.11,36.1 48.11,37.78 48.29,37.95 48.54,37.95 48.72,37.78 48.72,36.08 49,35.8 50.7,35.8 50.95,36.05 50.95,37.78 51.13,37.95 51.38,37.95 51.56,37.78 51.56,36.24 52,35.8 55.65,35.8 56.24,36.38 56.24,37.76 56.43,37.95 57.32,37.95 57.55,37.72 57.55,37.34
DDRA_DQ13: length 40.4
  TOP w0.152: IC13.P38 57.95,36.77 57.95,38.14 57.73,38.36 56.05,38.36 55.83,38.14 55.83,36.55 55.66,36.38 55.4,36.38 55.22,36.56 55.22,37.12 55.07,37.27 54.76,37.27 54.61,37.12 54.61,36.36 54.46,36.21 52.17,36.21 51.97,36.41 51.97,38.14 51.74,38.36 50.78,38.36 50.55,38.13 50.55,36.48 50.27,36.21 49.4,36.21 49.12,36.49 49.12,38.29 48.93,38.49 47.9,38.49 47.7,38.29 47.7,36.46 47.45,36.21 46.56,36.21 46.28,36.49 46.28,39.51 46.02,39.77 42.88,39.77 42.62,39.51 42.62,34.54 42.39,34.31 40.34,34.31 40.12,34.53 U9.A2
DDRA_DQ14: length 38.9
  TOP w0.127: U9.C2 40.51,36.61 41.12,36.61 ; IC13.R35 60.34,36.76 58.83,36.76 v2(58.58,37.01)
  TOP w0.152: 41.12,36.61 41.38,36.61 42.14,35.85 v1(42.14,35.74)
  BOTTOM w0.152: v1(42.14,35.74) 42.74,35.74 42.92,35.56 42.92,33.54 43.1,33.36 43.35,33.36 43.53,33.54 43.53,35.56 43.71,35.74 43.96,35.74 44.14,35.56 44.14,33.54 44.32,33.36 44.57,33.36 44.75,33.54 44.75,35.56 44.93,35.74 45.18,35.74 45.36,35.56 45.36,33.54 45.53,33.36 45.79,33.36 45.97,33.54 45.97,35.56 46.14,35.74 46.4,35.74 46.58,35.56 46.58,33.83 46.85,33.55 56.85,33.55 58.58,35.28 v2(58.58,37.01)
DDRA_DQ15: length 37.9
  TOP w0.127: v2(39.72,36.6) 39.32,37 U9.C3
  TOP w0.152: IC13.R36 59.94,37.16 59.16,37.16 v2(58.75,37.56)
  BOTTOM w0.102: v2(39.72,36.6) 40.14,36.18 41.85,36.18
  BOTTOM w0.152: 41.85,36.18 46.8,36.18 46.98,36 46.98,34.14 47.16,33.96 47.41,33.96 47.59,34.14 47.59,36 47.77,36.18 48.02,36.18 48.2,36 48.2,34.14 48.38,33.96 48.63,33.96 48.81,34.14 48.81,36 48.99,36.18 49.24,36.18 49.42,36 49.42,34.14 49.6,33.96 49.85,33.96 50.03,34.14 50.03,36 50.21,36.18 50.46,36.18 50.64,36 50.64,34.14 50.82,33.96 56.68,33.96 58.16,35.43 58.16,37.38 58.35,37.56 v2(58.75,37.56)
DDRA_DQSN0: length 37.7
  TOP w0.127: IC13.J36 59.83,32.49 59.41,32.49 59.34,32.42 58.46,32.42 58.45,32.41 58.42,32.41 ; U9.G3 v2(39.72,39.8)
  TOP w0.152: v1(55.14,32.18) 55.37,32.41 58.42,32.41
  BOTTOM w0.152: v2(39.72,39.8) 39.47,39.55 39.14,39.55 38.84,39.25 38.84,34.15 39.21,33.78 39.21,31.57 39.61,31.17 40.18,31.17 40.58,31.57 40.58,32.12 40.77,32.31 41.08,32.31 41.3,32.09 41.3,31.6 41.74,31.17 42.31,31.17 42.71,31.57 42.71,32.12 42.9,32.31 43.22,32.31 43.44,32.09 43.44,31.6 43.88,31.17 44.44,31.17 44.85,31.57 44.85,32.12 45.03,32.31 45.35,32.31 45.57,32.09 45.57,31.6 46.01,31.17 46.58,31.17 46.98,31.57 46.98,32.12 47.17,32.31 47.48,32.31 47.71,32.09 47.71,31.6 48.14,31.17 48.71,31.17 49.11,31.57 49.11,32.06 49.46,32.41 54.91,32.41 v1(55.14,32.18)
DDRA_DQSN1: length 41.6
  TOP w0.127: IC13.N35 60.55,35.57 60.16,35.18 59.73,35.18 59.45,34.9 57.6,34.9 57.59,34.88
  TOP w0.152: U9.B7 36.37,36.45 37.41,36.45 37.74,36.78 37.74,39.61 37.92,39.79 38.3,39.79 38.51,39.59 38.51,33.74 39.26,32.99 43.05,32.99 43.94,33.89 43.94,37.9 44.11,38.07 44.79,38.07 44.96,37.9 44.96,35.32 45.39,34.88 57.59,34.88
DDRA_DQSP0: length 37.7
  TOP w0.127: 58.42,32.71 58.45,32.71 58.46,32.7 59.23,32.7 59.29,32.77 60.45,32.77 60.75,32.47 IC13.J35 ; v2(39.72,39) 39.32,39.4 U9.F3
  TOP w0.152: 58.42,32.71 55.37,32.71 v1(55.14,32.94)
  BOTTOM w0.152: v1(55.14,32.94) 54.91,32.71 49.34,32.71 48.81,32.18 48.81,31.69 48.59,31.47 48.27,31.47 48.01,31.73 48.01,32.21 47.61,32.62 47.04,32.62 46.68,32.25 46.68,31.69 46.45,31.47 46.14,31.47 45.88,31.73 45.88,32.21 45.48,32.62 44.91,32.62 44.54,32.25 44.54,31.69 44.32,31.47 44,31.47 43.74,31.73 43.74,32.21 43.34,32.62 42.77,32.62 42.41,32.25 42.41,31.69 42.18,31.47 41.87,31.47 41.61,31.73 41.61,32.21 41.21,32.62 40.64,32.62 40.27,32.25 40.27,31.69 40.05,31.47 39.74,31.47 39.51,31.69 39.51,33.91 39.14,34.28 39.14,39.12 39.27,39.25 39.47,39.25 v2(39.72,39)
DDRA_DQSP1: length 41.6
  TOP w0.127: IC13.N36 59.73,35.57 59.44,35.28 59.34,35.18 57.6,35.18 57.59,35.19 57.56,35.19
  TOP w0.152: U9.C7 36.37,36.75 37.29,36.75 37.44,36.91 37.44,39.74 37.8,40.09 38.43,40.09 38.81,39.71 38.81,33.87 39.38,33.29 42.92,33.29 43.64,34.01 43.64,38.02 43.99,38.37 44.91,38.37 45.26,38.02 45.26,35.44 45.52,35.19 56.22,35.19 56.39,35.36 56.39,35.65 56.58,35.85 56.95,35.85 57.15,35.65 57.15,35.31 57.27,35.19 57.56,35.19
DDRA_ODT0: length 30.6
  TOP w0.102: 38.45,42.32 38.56,42.21 40.53,42.21 U9.K1
  TOP w0.152: v1(43.94,54.49) 43.94,52.41 42.2,50.67 38.07,50.67 37.9,50.5 37.9,42.87 38.45,42.32 ; R201.1 v1(53.19,52.83)
  BOTTOM w0.152: v1(43.94,54.49) 51.53,54.49 v1(53.19,52.83)
DDRA_ODT0_R: length 6
  TOP w0.152: IC13.AM36 59.14,51.58 57.1,51.58 55.85,52.83 R201.2
DDRA_RASN: length 28.6
  TOP w0.152: R202.1 51.59,52.59 v1(51.94,52.95) ; v1(43.26,54.09) 43.26,52.3 42.04,51.08 37.74,51.08 37.49,50.83 37.49,42.52 38.21,41.8 U9.J3
  BOTTOM w0.152: v1(43.26,54.09) 43.36,53.99 50.9,53.99 v1(51.94,52.95)
DDRA_RASN_R: length 7.2
  TOP w0.152: R202.2 55.84,52.26 56.93,51.17 58.75,51.17 IC13.AM37
DDRA_REF\G: length 10.2
  TOP w0.381: v2(66.75,41.57) 66.35,41.17 IC13.Y28 ; v2(66.75,37.56) 66.35,37.17 IC13.R28 ; v2(66.75,35.96) 66.35,35.57 IC13.N28
  BOTTOM w0.381: C293.2 67.15,37.96 v2(66.75,37.56) ; C293.2 67.47,36.77 R191.2 67.47,36.43 67.09,36.05 66.84,36.05 v2(66.75,35.96) 66.33,35.96 65.95,35.58 C294.1 ; C293.2 67.47,39.16 R192.1 C288.2 67.47,40.86 66.76,41.57 v2(66.75,41.57)
DDRA_RESETN\G: length 55.4
  TOP w0.152: R617.1 v1(46.33,43.73)
  BOTTOM w0.152: R189.2 46.62,40.77 46.33,41.06 v1(46.33,43.73) 42.55,43.73 42.2,43.38 39.92,43.38 39.89,43.41 39.09,43.41 38.05,43.41 37.86,43.22 34.45,43.22 31.17,39.93 31.17,35.27 36.84,29.59 R619.1 37.96,20.74 R620.2 R638.1
DDRA_VREF_CA: length 9.3
  TOP w0.406: U9.M8 v2(34.92,43.8)
  BOTTOM w0.508: C468.2 C467.1 30.33,46.61 R625.1 30.23,45.21 R624.2 30.25,43.79 C466.1 C465.1 34.91,43.79 v2(34.92,43.8)
DDRA_VREF_DQ: length 10.8
  TOP w0.356: v2(41.66,41.02) 41.64,41 U9.H1
  BOTTOM w0.508: v2(41.66,41.02) 41.27,41.02 40.65,40.4 38.6,40.4 C461.1 C462.1 C463.1 C464.2 38.2,35.28 R623.2 R622.1
DDRA_WEN: length 35.1
  TOP w0.152: U9.L3 v2(38.92,43) ; v1(53.19,40.26) R231.1
  BOTTOM w0.152: v1(53.19,40.26) 53.19,39.92 53.05,39.78 52.2,39.78 52.02,39.95 52.02,40.18 51.84,40.36 51.59,40.36 51.41,40.18 51.41,39.95 51.23,39.78 50.98,39.78 50.8,39.95 50.8,40.18 50.62,40.36 50.37,40.36 50.19,40.18 50.19,39.8 50.01,39.62 49.76,39.62 49.58,39.8 49.58,40.18 49.4,40.36 49.15,40.36 48.97,40.18 48.97,39.8 48.79,39.62 48.54,39.62 48.36,39.8 48.36,40.18 48.18,40.36 47.93,40.36 47.75,40.18 47.75,39.95 47.57,39.78 47.32,39.78 47.14,39.95 47.14,40.18 46.96,40.36 46.71,40.36 46.53,40.18 46.53,39.95 46.35,39.78 46.1,39.78 45.92,39.95 45.92,42.79 45.74,42.97 45.49,42.97 45.31,42.79 45.31,39.95 45.14,39.78 44.88,39.78 44.7,39.95 44.7,42.79 44.53,42.97 44.27,42.97 44.09,42.79 44.09,39.95 43.92,39.78 43.66,39.78 43.48,39.95 43.48,41.99 43.26,42.21 39.09,42.21 38.92,42.39 v2(38.92,43)
DDRA_WEN_R: length 6.1
  TOP w0.127: IC13.Y36 59.54,40.76 59.54,40.21 59.31,39.98 57.9,39.98 57.89,39.99 57.02,39.99
  TOP w0.152: R231.2 54.86,40.28 56.5,40.28 56.8,39.99 57.02,39.99
DDRB_ADDR0: length 33.4
  TOP w0.152: U10.N3 44.91,13.41 v2(44.51,13.81) ; v1(44.81,28.61) 45.92,27.5 R281.1
  BOTTOM w0.102: v2(44.51,13.81) 44.51,16.6 44.55,16.64
  BOTTOM w0.152: v1(44.81,28.61) 46.71,28.61 46.89,28.43 46.89,28.18 46.71,28 45.26,28 45.1,27.84 45.1,27.55 45.26,27.39 46.91,27.39 47.19,27.11 47.19,23.15 46.94,22.9 45.75,22.9 45.47,22.62 45.47,17.55 44.55,16.64
DDRB_ADDR0_R: length 3.3
  TOP w0.127: 57.02,27.22 58.71,27.22 59.06,27.57 IC13.C37
  TOP w0.152: 57.02,27.22 56.88,27.22 56.6,27.5 R281.2
DDRB_ADDR1: length 34.4
  TOP w0.152: v2(44.51,10.61) U10.P7 ; R261.1 65.79,19.19 65.05,18.45 60.96,18.45 v1(60.3,19.11)
  BOTTOM w0.152: v2(44.51,10.61) 44.51,10.79 45.81,12.09 45.81,14.59 46.91,15.7 46.91,17 48.97,19.06 56.15,19.06 56.72,19.63 56.72,21.89 57.21,22.38 58.49,22.38 58.95,21.91 58.95,19.8 59.64,19.11 v1(60.3,19.11)
DDRB_ADDR1_R: length 7.6
  TOP w0.127: 65.95,24.28 65.95,27.97 IC13.D29
  TOP w0.152: R261.2 65.79,23.84 65.95,24 65.95,24.28
DDRB_ADDR2: length 32
  TOP w0.152: U10.P3 44.41,13.11 v2(44.51,13.01) ; v1(44.59,26.92) R289.1
  BOTTOM w0.102: v2(44.51,13.01) 44.13,13.39 44.13,15.08 43.75,15.46 43.75,16.41 43.98,16.64
  BOTTOM w0.152: v1(44.59,26.92) 46.57,26.92 46.79,26.71 46.79,25.59 46.53,25.34 44.22,25.34 44.07,25.18 44.07,24.88 44.22,24.73 46.56,24.73 46.79,24.5 46.79,23.53 46.56,23.3 45.47,23.3 45.06,22.9 45.06,17.72 43.98,16.64
DDRB_ADDR2_R: length 4.6
  TOP w0.152: IC13.B38 56.75,26.77 56.59,26.92 R289.2
DDRB_ADDR3: length 32.8
  TOP w0.102: U10.N2 44.51,14.61 44.51,16.64
  TOP w0.152: v1(46.08,18.2) 44.81,18.2 44.51,17.91 44.51,16.64 ; v1(62.84,19.42) 62.36,19.9 R287.1
  BOTTOM w0.152: v1(62.84,19.42) 62.84,19.61 61.49,20.95 60.63,20.95 60.17,21.41 60.17,23.86 59.7,24.33 56.02,24.33 55.5,23.81 55.5,20.9 54.88,20.28 47.78,20.28 47.3,19.8 47.3,19.21 47.13,19.05 46.85,19.05 46.69,19.21 46.69,19.54 46.51,19.72 46.25,19.72 46.08,19.54 v1(46.08,18.2)
DDRB_ADDR3_R: length 6.1
  TOP w0.127: IC13.B32 63.15,26.7 62.75,26.3 62.75,24.41
  TOP w0.152: R287.2 62.36,23.55 62.75,23.94 62.75,24.41
DDRB_ADDR4: length 31.5
  TOP w0.102: v2(43.18,11.05) 43.7,10.53 43.7,9.83 U10.P8
  TOP w0.152: R268.1 v1(43.03,24.07)
  BOTTOM w0.152: v2(43.18,11.05) 42.14,12.09 42.14,15.95 44.25,18.06 44.25,23.07 44.07,23.25 42.14,23.25 41.96,23.43 41.96,23.89 42.14,24.07 v1(43.03,24.07)
DDRB_ADDR4_R: length 7.1
  TOP w0.127: 60.07,25.17 60.36,25.46 60.36,27.18 IC13.C35
  TOP w0.152: R268.2 58.97,24.07 60.07,25.17
DDRB_ADDR5: length 35.5
  TOP w0.102: U10.P2 43.71,14.61 43.71,16.64
  TOP w0.152: 43.71,16.64 43.71,18.02 v1(46.08,20.38) ; v1(60.64,21.59) R272.1
  BOTTOM w0.152: v1(60.64,21.59) 60.64,21.84 60.82,22.02 62.13,22.02 62.31,22.2 62.31,22.45 62.13,22.63 60.87,22.63 60.63,22.87 60.63,23.89 60.87,24.13 62.2,24.13 62.38,24.31 62.38,24.56 62.2,24.74 60.02,24.74 55.42,24.74 55.09,24.41 55.09,21.07 54.71,20.69 46.39,20.69 v1(46.08,20.38)
DDRB_ADDR5_R: length 5.9
  TOP w0.127: IC13.D33 61.94,27.96 61.94,25.56 61.53,25.15 61.53,24.45 61.36,24.28
  TOP w0.152: 61.36,24.28 60.64,23.56 R272.2
DDRB_ADDR6: length 30.1
  TOP w0.152: R266.1 v1(42.39,24.64) ; U10.R8 v2(42.91,9.01)
  BOTTOM w0.152: v2(42.91,9.01) 41.73,10.19 41.73,16.12 43.84,18.23 43.84,21.96 42.95,22.85 41.97,22.85 41.55,23.26 41.55,24.22 41.98,24.64 v1(42.39,24.64)
DDRB_ADDR6_R: length 7.7
  TOP w0.152: IC13.B36 59.95,25.62 58.97,24.64 R266.2
DDRB_ADDR7: length 35.6
  TOP w0.102: U10.R2 43.31,14.22 42.93,14.61 42.93,16.64
  TOP w0.152: 42.93,16.64 42.93,17.92 v1(46.1,21.09) ; v1(62.93,21.59) R284.1
  BOTTOM w0.152: v1(62.93,21.59) 62.93,22.81 62.62,23.11 61.49,23.11 61.32,23.29 61.32,23.55 61.49,23.72 62.65,23.72 62.84,23.91 62.84,24.93 62.62,25.15 54.97,25.15 54.69,24.87 54.69,21.35 54.43,21.09 v1(46.1,21.09)
DDRB_ADDR7_R: length 2.8
  TOP w0.152: R284.2 62.93,23.55 63.15,23.77 IC13.A32
DDRB_ADDR8: length 33.1
  TOP w0.152: R264.1 v1(42.91,25.21) ; U10.T8 v2(42.11,9.01)
  BOTTOM w0.152: v2(42.11,9.01) 41.33,9.8 41.33,16.28 42.91,17.87 42.91,22.05 42.52,22.44 41.38,22.44 41.07,22.75 41.07,24.93 41.35,25.21 v1(42.91,25.21)
DDRB_ADDR8_R: length 5.8
  TOP w0.127: 59.56,26.13 59.56,27.17 IC13.C36
  TOP w0.152: R264.2 56.62,25.21 56.78,25.04 58.8,25.04 59.56,25.8 59.56,26.13
DDRB_ADDR9: length 33.3
  TOP w0.152: v2(44.94,12.61) 44.93,12.6 44.22,12.6 43.41,13.41 U10.R3 ; R280.1 v1(63.5,19.32)
  BOTTOM w0.102: 45.4,16.64 45.31,16.55 45.31,15.53 44.94,15.15 v2(44.94,12.61)
  BOTTOM w0.152: v1(63.5,19.32) 63.14,18.96 62.65,18.96 62.31,19.3 62.31,19.56 61.32,20.55 60.46,20.55 59.77,21.24 59.77,23.43 59.27,23.93 56.38,23.93 55.91,23.46 55.91,20.73 55.05,19.87 48.64,19.87 45.4,16.64
DDRB_ADDR9_R: length 7.6
  TOP w0.127: IC13.D32 63.56,27.96 63.56,24.28
  TOP w0.152: R280.2 63.5,23.5 63.56,23.56 63.56,24.28
DDRB_ADDR10: length 36.2
  TOP w0.152: v1(64.07,21.56) R265.1 ; U10.L7 v2(46.51,10.83)
  BOTTOM w0.152: v1(64.07,21.56) 64.07,22.6 64.36,22.9 64.87,22.9 65.13,22.64 65.13,16.42 64.8,16.09 61.08,16.09 60.77,15.79 60.77,12.37 60.59,12.19 60.34,12.19 60.16,12.37 60.16,13.93 59.98,14.11 59.73,14.11 59.55,13.93 59.55,12.37 59.37,12.19 48.82,12.19 47.47,10.83 v2(46.51,10.83)
DDRB_ADDR10_R: length 5
  TOP w0.152: R265.2 64.07,24.38 64.52,24.83 64.52,26.53 IC13.C29
DDRB_ADDR11: length 31.8
  TOP w0.152: U10.R7 42.86,10.67 v1(40.87,10.67) ; R263.1 v1(42.46,25.78)
  BOTTOM w0.152: v1(40.87,10.67) 40.87,16.4 42.46,17.99 42.46,21.61 42.06,22.01 40.99,22.01 40.61,22.39 40.61,25.44 40.96,25.78 v1(42.46,25.78)
DDRB_ADDR11_R: length 5.7
  TOP w0.152: R263.2 56.65,25.78 56.98,25.45 58.64,25.45 IC13.A37
DDRB_ADDR12: length 35.1
  TOP w0.152: U10.N7 v2(45.31,9.81) ; R277.1 v1(61.79,19.44)
  BOTTOM w0.152: v1(61.79,19.44) 61.79,17.52 61.57,17.31 58.4,17.31 58.14,17.56 58.14,21.41 57.99,21.56 57.68,21.56 57.53,21.41 57.53,18.45 57.33,18.25 49.31,18.25 47.73,16.67 47.73,15.36 46.62,14.26 46.62,11.63 45.44,10.45 45.44,9.94 v2(45.31,9.81)
DDRB_ADDR12_R: length 4.9
  TOP w0.127: 62.33,24.45 62.33,24.73 62.49,24.89 62.49,26.55 62.76,26.82 62.76,27.18 IC13.C32
  TOP w0.152: R277.2 61.79,23.56 62.33,24.1 62.33,24.45
DDRB_ADDR13: length 34.6
  TOP w0.152: v2(42.91,13.81) U10.T3 ; R262.1 v1(43.31,26.35)
  BOTTOM w0.102: 43.4,16.64 42.93,16.16 42.93,13.82 v2(42.91,13.81)
  BOTTOM w0.152: 43.4,16.64 44.65,17.89 44.65,23.36 45.01,23.71 46.1,23.71 46.28,23.89 46.28,24.17 46.13,24.32 43.89,24.32 43.66,24.55 43.66,25.52 43.89,25.74 46.08,25.74 46.25,25.92 46.25,26.2 46.1,26.35 v1(43.31,26.35)
DDRB_ADDR13_R: length 3.2
  TOP w0.127: 57.02,26.35 57.61,26.35 57.62,26.36 58.75,26.36 IC13.B37
  TOP w0.152: 57.02,26.35 R262.2
DDRB_ADDR14: length 32.4
  TOP w0.152: R288.1 60.96,19.79 v1(60.36,19.79) ; U10.T7 v2(42.91,9.81)
  BOTTOM w0.152: v1(60.36,19.79) 59.54,19.79 59.36,19.96 59.36,23.27 59.11,23.52 56.57,23.52 56.31,23.27 56.31,19.8 55.98,19.47 48.8,19.47 46.51,17.17 46.51,15.87 45.4,14.76 45.4,12.3 v2(42.91,9.81)
DDRB_ADDR14_R: length 7
  TOP w0.127: IC13.C33 62.34,27.55 62.34,26.75 62.24,26.66 62.24,25.3 61.92,24.98 61.92,24.4
  TOP w0.152: R288.2 61.21,23.56 61.92,24.27 61.92,24.4
DDRB_BA0: length 36.6
  TOP w0.102: U10.M2 45.31,14.61 45.31,15.8 46.15,16.64
  TOP w0.152: v1(46.84,22.01) 46.84,17.33 46.15,16.64 ; R275.1 v1(66.36,21.58)
  BOTTOM w0.152: v1(66.36,21.58) 66.36,25.22 66.03,25.55 54.57,25.55 54.28,25.26 54.28,21.83 54,21.55 47.04,21.55 46.84,21.75 v1(46.84,22.01)
DDRB_BA0_R: length 2.8
  TOP w0.152: IC13.A28 66.36,25.96 R275.2
DDRB_BA1: length 37
  TOP w0.152: U10.N8 44.51,9.81 v2(44.51,9.81) ; v1(61.19,19.11) 61.44,18.86 64.88,18.86 65.21,19.19 R267.1
  BOTTOM w0.152: v2(44.51,9.81) 44.93,10.23 44.93,10.57 46.22,11.85 46.22,14.42 47.32,15.53 47.32,16.84 49.14,18.66 56.87,18.66 57.13,18.91 57.13,21.72 57.38,21.97 58.32,21.97 58.55,21.74 58.55,18.93 58.9,18.58 60.65,18.58 v1(61.19,19.11)
DDRB_BA1_R: length 2.9
  TOP w0.152: R267.2 65.21,24.26 65.46,24.5 65.46,25.87 IC13.A29
DDRB_BA2: length 34
  TOP w0.152: U10.M3 46.52,12.6 48.16,12.6 v2(48.31,12.45) ; v1(64.64,19.37) R270.1
  BOTTOM w0.152: v2(48.31,12.45) 48.46,12.6 58.88,12.6 59.15,12.86 59.15,16.31 59.33,16.5 59.58,16.5 59.76,16.32 59.76,14.69 59.93,14.52 60.19,14.52 60.37,14.69 60.37,16.32 60.54,16.5 63.25,16.5 63.42,16.67 63.42,18.53 63.6,18.71 63.85,18.71 64.03,18.53 64.03,16.67 64.21,16.5 64.47,16.5 64.64,16.67 v1(64.64,19.37)
DDRB_BA2_R: length 6.1
  TOP w0.152: IC13.B29 64.92,26.14 64.92,24.68 64.64,24.4 R270.2
DDRB_CASN: length 35
  TOP w0.102: U10.K3 47.31,13.41 46.91,13.82 46.91,15.54
  TOP w0.152: R278.1 49.14,29.78 v1(48.24,28.88) ; v1(48.24,22.01) 48.24,21.57 47.7,21.04 47.7,16.98 46.91,16.19 46.91,15.54
  BOTTOM w0.152: v1(48.24,28.88) 48.24,27.85 48.49,27.6 51.23,27.6 51.49,27.34 51.49,25.18 51.26,24.95 48.24,24.95 48.01,24.73 48.01,23.79 48.26,23.53 50.93,23.53 51.08,23.38 51.08,23.07 50.93,22.92 48.59,22.92 48.24,22.57 v1(48.24,22.01)
DDRB_CASN_R: length 4.4
  TOP w0.127: IC13.D36 59.55,28.77 58.19,28.77 57.19,29.78 57.02,29.78
  TOP w0.152: 57.02,29.78 R278.2
DDRB_CKE0: length 42.5
  TOP w0.102: U10.K9 v2(46.91,9.01)
  TOP w0.127: IC13.D27 v2(67.55,27.97)
  BOTTOM w0.152: v2(67.55,27.97) 67.59,27.93 R197.1 67.59,23.71 66.83,22.95 66.83,18.07 66.65,17.89 66.4,17.89 66.22,18.07 66.22,19.85 66.04,20.03 65.79,20.03 65.61,19.85 65.61,15.89 65.41,15.68 61.46,15.68 61.18,15.4 61.18,12.09 60.87,11.78 49.06,11.78 46.91,9.64 v2(46.91,9.01)
DDRB_CKN0: length 30.8
  TOP w0.152: R282.1 52.44,23.03 41.4,23.03 41,22.62 41,22.35 R644.1 41,21.59 41,21.21 R643.2 41,20.45 41,20.17 R645.1 41,18.95 41,13.5 42.91,11.58 46.8,11.58 47.52,10.86 47.52,10.42 U10.K7
DDRB_CKN0_R: length 10.1
  TOP w0.127: 60.65,24.87 60.66,24.88 60.72,24.88 60.91,25.07 60.91,25.56 61.15,25.8 61.15,26.36 IC13.B34
  TOP w0.152: R282.2 54.24,23.03 58.81,23.03 60.65,24.87
DDRB_CKP0: length 30.3
  TOP w0.152: R286.1 52.44,22.72 41.53,22.72 41.3,22.49 41.3,22.35 R641.1 41.3,21.59 41.3,21.21 R642.2 41.3,20.45 41.3,20.17 R645.2 41.3,18.95 41.3,13.63 43.04,11.89 46.92,11.89 47.83,10.98 47.83,10.5 U10.J7
DDRB_CKP0_R: length 10.3
  TOP w0.127: 60.87,24.65 60.88,24.66 60.88,24.72 61.13,24.97 61.13,25.47 61.37,25.71 61.37,25.79 IC13.A34
  TOP w0.152: 60.87,24.65 58.94,22.72 58.17,22.72 58.04,22.59 58.04,22.35 57.9,22.21 57.42,22.21 57.28,22.35 57.28,22.56 57.11,22.72 54.24,22.72 R286.2
DDRB_CSN0: length 35.2
  TOP w0.102: 46.11,15.28 46.11,14.61 U10.L2
  TOP w0.152: v1(47.6,22.01) 47.6,21.51 47.29,21.21 47.29,17.15 46.11,15.97 46.11,15.28 ; v1(47.6,28.42) 49.19,28.42 49.4,28.64 R269.1
  BOTTOM w0.152: v1(47.6,22.01) 47.6,25.18 47.78,25.36 50.8,25.36 50.98,25.54 50.98,25.79 50.8,25.97 47.78,25.97 47.6,26.15 47.6,26.4 47.78,26.58 50.8,26.58 50.98,26.76 50.98,27.01 50.8,27.19 47.88,27.19 47.6,27.47 v1(47.6,28.42)
DDRB_CSN0_R: length 3.5
  TOP w0.127: 57.02,28.22 57.34,27.9 58.44,27.9 58.9,28.37 IC13.D37
  TOP w0.152: 57.02,28.22 56.6,28.64 R269.2
DDRB_DM0: length 38.1
  TOP w0.127: 69.15,24.28 69.15,27.17 IC13.C25
  TOP w0.152: v2(51.72,10.61) 51.32,10.21 U10.E7 ; v1(69.15,20.99) 69.15,24.28
  BOTTOM w0.102: 53.7,10.95 52.72,10.95 52.67,10.99 52.1,10.99 v2(51.72,10.61)
  BOTTOM w0.152: v1(69.15,20.99) 69.14,20.99 69.14,15.84 68.96,15.66 68.71,15.66 68.53,15.84 68.53,17.82 68.35,17.99 68.1,17.99 67.92,17.82 67.92,16.17 66.62,14.87 62.35,14.87 61.99,14.52 61.99,11.24 61.7,10.95 53.7,10.95
DDRB_DM1: length 43.7
  TOP w0.152: IC13.A22 71.23,25.89 71.23,19.43 66.49,14.69 66.14,14.69 65.96,14.51 65.96,10.56 65.79,10.38 65.56,10.38 65.35,10.58 65.35,14.51 65.18,14.69 64.92,14.69 64.75,14.52 64.75,10.55 64.57,10.38 64.31,10.38 64.14,10.55 64.14,13.14 63.83,13.45 59.69,13.45 58.85,12.6 52.43,12.6 52.11,12.92 U10.D3
DDRB_DQ0: length 41.1
  TOP w0.152: v2(49.31,9.81) 48.91,9.41 U10.H8 ; IC13.B16 75.95,26.54 76.59,25.9 76.59,25.89 76.7,25.77 76.7,24.59 76.71,24.58 76.71,18.88 v1(76.77,18.83)
  BOTTOM w0.152: v1(76.77,18.83) 73.66,18.83 69.95,15.12 69.95,13.28 66.81,10.14 66.47,10.14 53.13,10.14 52.81,9.81 v2(49.31,9.81)
DDRB_DQ1: length 44.6
  TOP w0.102: U10.F8 50.13,9.03 50.13,7.84 50.58,7.39 51.92,7.39
  TOP w0.127: IC13.B17 75.56,26.36 75.56,25.81 75.9,25.46 75.9,24.41
  TOP w0.152: 75.9,24.41 75.9,17.42 66.93,8.45 63.74,8.45 63.49,8.21 63.49,7.57 63.31,7.39 63.06,7.39 62.88,7.57 62.88,8.13 62.7,8.31 62.45,8.31 62.27,8.13 62.27,7.57 62.1,7.39 61.84,7.39 61.66,7.57 61.66,8.13 61.49,8.31 61.23,8.31 61.05,8.13 61.05,7.67 60.77,7.39 51.92,7.39
DDRB_DQ2: length 43.3
  TOP w0.102: U10.F7 50.89,9.83 50.89,8.49 51.59,7.8 55.63,7.8
  TOP w0.127: IC13.A17 75.31,25.81 75.31,25.16 75.5,24.97 75.5,24.41
  TOP w0.152: 55.63,7.8 58.03,7.8 58.21,7.98 58.21,8.73 58.39,8.91 58.64,8.91 58.82,8.73 58.82,7.98 59,7.8 59.25,7.8 59.43,7.98 59.43,8.73 59.61,8.91 59.86,8.91 60.04,8.73 60.04,7.98 60.22,7.8 60.47,7.8 60.65,7.98 60.65,8.68 60.83,8.86 66.76,8.86 75.5,17.59 75.5,24.41
DDRB_DQ3: length 43.9
  TOP w0.102: 48.7,7.47 48.49,7.67 48.49,9.79 U10.H7
  TOP w0.127: IC13.A16 76.31,25.61 76.31,24.41
  TOP w0.152: 48.7,7.47 49.18,6.99 66.04,6.99 76.31,17.26 76.31,24.41
DDRB_DQ4: length 40
  TOP w0.102: U10.F2 50.09,14.63 50.09,15.81 49.33,16.58 49.33,16.64
  TOP w0.127: IC13.B25 68.36,26.37 68.36,25.69 68.28,25.61 68.28,24.28
  TOP w0.152: 49.33,16.64 49.33,19.09 49.51,19.26 49.76,19.26 49.94,19.09 49.94,18.33 50.11,18.15 50.37,18.15 50.55,18.33 50.55,20.92 50.83,21.2 59.13,21.2 59.44,20.89 59.44,17.39 59.69,17.13 65.48,17.13 68.28,19.94 68.28,24.28
DDRB_DQ5: length 39.4
  TOP w0.102: 51.83,16.64 51.7,16.5 51.7,13.72 51.38,13.41 U10.E3
  TOP w0.127: IC13.A25 68.75,25.25 68.69,25.18 68.69,24.28
  TOP w0.152: 68.69,24.28 68.69,19.77 65.65,16.73 59.33,16.73 59.03,17.03 59.03,20.53 58.78,20.79 51.23,20.79 51,20.56 51,17.56 51.23,17.34 52.93,17.34 53.09,17.18 53.09,16.88 52.93,16.73 51.92,16.73 51.83,16.64
DDRB_DQ6: length 38.6
  TOP w0.102: U10.G2 49.33,14.59 49.33,15.91 48.92,16.32 48.92,16.64
  TOP w0.127: 67.88,24.28 67.88,25.89 IC13.A26
  TOP w0.152: 67.88,24.28 67.88,20.11 65.31,17.54 60.12,17.54 59.84,17.82 59.84,21.25 59.49,21.6 50.42,21.6 50.14,21.32 50.14,19.95 49.99,19.8 49.71,19.8 49.53,19.98 49.53,20.53 49.35,20.71 49.1,20.71 48.92,20.53 48.92,16.64
DDRB_DQ7: length 36.9
  TOP w0.152: v1(67.39,22.01) 67.39,26.2 IC13.B26 ; U10.H3 49.25,13.07 49.25,11.34 v2(49.38,11.21)
  BOTTOM w0.152: v2(49.38,11.21) 49.54,11.38 61.25,11.38 61.58,11.72 61.58,15.1 61.76,15.28 65.89,15.28 66.17,15.56 66.17,16.88 66.35,17.06 66.6,17.06 66.78,16.88 66.78,16.4 66.98,16.19 67.18,16.19 67.39,16.39 v1(67.39,22.01)
DDRB_DQ8: length 40.8
  TOP w0.102: 55.63,9.56 55.49,9.56 55.26,9.79 54.09,9.79 U10.B8
  TOP w0.127: 73.57,24.41 73.57,25.95 IC13.A19
  TOP w0.152: 55.63,9.56 v1(56.6,9.56) ; 73.57,24.41 73.57,18.47 72.31,17.21 72.09,16.99 v1(72.09,16.42)
  BOTTOM w0.152: v1(56.6,9.56) 57.01,9.16 70.56,9.16 70.87,9.46 70.87,12.69 71.05,12.86 71.3,12.86 71.48,12.69 71.48,10.45 71.66,10.28 71.91,10.28 72.09,10.45 v1(72.09,16.42)
DDRB_DQ9: length 40.9
  TOP w0.102: 55.33,9.02 53.31,9.02 U10.C8
  TOP w0.127: IC13.B19 73.97,26.35 73.97,24.41
  TOP w0.152: v1(56.62,8.42) 56.02,9.02 55.33,9.02 ; 73.97,24.41 73.97,18.22 v1(73.03,17.28)
  BOTTOM w0.152: v1(73.03,17.28) 73.03,8.68 72.85,8.5 72.6,8.5 72.42,8.67 72.42,9.38 72.24,9.56 71.99,9.56 71.81,9.38 71.81,8.78 71.45,8.42 v1(56.62,8.42)
